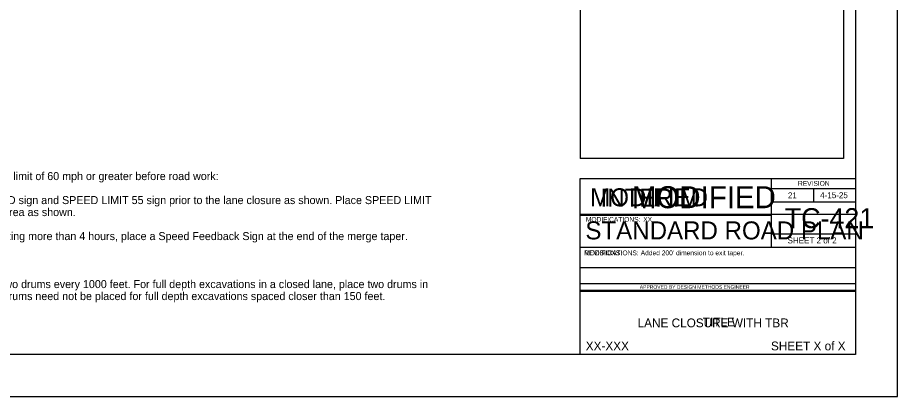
# Model space of a CAD drawing. Extents: x -2135039 to 114557, y -2139150 to -409929.
# Drawn here: x -2130293 to -2128095, y -2139150 to -2138203 of the extents above; entities that cross this region are included whole.
import ezdxf

# ---------------------------------------------------------------- set-up
doc = ezdxf.new("R2010")
doc.units = 0
for name, color, linetype in [('dsnDOTLogo', 7, 'Continuous'), ('dsnNonPlotable', 7, 'Continuous'), ('dsnStdBlock', 7, 'Continuous'), ('dsnstdblockInterim', 7, 'Continuous'), ('dsnStdLogo', 7, 'Continuous'), ('dsnstdModifiedBlock', 7, 'Continuous'), ('Level 1', 7, 'Continuous'), ('Level 12', 7, 'Continuous'), ('StdNote', 7, 'Continuous')]:
    doc.layers.add(name, color=color, linetype=linetype)

msp = doc.modelspace()

# ---------------------------------------------------------------- linework, layer by layer
at = {"layer": 'dsnDOTLogo'}
msp.add_lwpolyline([(-2131438.9, -2139150.4), (-2128095, -2139150.4), (-2128095, -2136566.4), (-2131438.9, -2136566.4)], close=True, dxfattribs=at)
at = {"layer": 'dsnNonPlotable'}
for p, q in [((-2128887.5, -2137085.9), (-2128887.5, -2138555.9)), ((-2128229.5, -2137085.9), (-2128229.5, -2138555.9)), ((-2128229.5, -2138555.9), (-2128887.5, -2138555.9))]:
    msp.add_line(p, q, dxfattribs=at)
at = {"layer": 'dsnStdLogo'}
for p, q in [((-2128410.4, -2138605.9), (-2128410.4, -2138697.3)), ((-2128410.4, -2138630.9), (-2128199.5, -2138630.9)), ((-2128304.9, -2138630.9), (-2128304.9, -2138664.1)), ((-2128410.4, -2138664.1), (-2128199.5, -2138664.1)), ((-2128887.5, -2138697.3), (-2128410.4, -2138697.3)), ((-2128410.4, -2138697.3), (-2128410.4, -2138777.3)), ((-2128199.5, -2138745.1), (-2128410.4, -2138745.1)), ((-2128887.5, -2138777.3), (-2128199.5, -2138777.3)), ((-2128887.5, -2138828.3), (-2128199.5, -2138828.3)), ((-2128887.5, -2138868.3), (-2128199.5, -2138868.3)), ((-2128887.5, -2138887.3), (-2128199.5, -2138887.3))]:
    msp.add_line(p, q, dxfattribs=at)
msp.add_lwpolyline([(-2128887.5, -2138605.9), (-2128199.5, -2138605.9), (-2128199.5, -2139045.9), (-2128887.5, -2139045.9)], close=True, dxfattribs=at)
at = {"layer": 'dsnstdModifiedBlock'}
for p, q in [((-2128887.5, -2138695), (-2128199.5, -2138695)), ((-2128887.5, -2138885), (-2128199.5, -2138885))]:
    msp.add_line(p, q, dxfattribs=at)
msp.add_lwpolyline([(-2128887.5, -2138605.9), (-2128199.5, -2138605.9), (-2128199.5, -2139045.9), (-2128887.5, -2139045.9)], close=True, dxfattribs=at)
at = {"layer": 'Level 1'}
msp.add_lwpolyline([(-2131334.4, -2137035.9), (-2128199.5, -2137035.9), (-2128199.5, -2139045.9), (-2131334.4, -2139045.9)], close=True, dxfattribs=at)
at = {"layer": 'Level 12'}
msp.add_lwpolyline([(-2128887.5, -2138605.9), (-2128199.5, -2138605.9), (-2128199.5, -2139045.9), (-2128887.5, -2139045.9)], close=True, dxfattribs=at)

# ---------------------------------------------------------------- texts
at = {"layer": 'dsnNonPlotable'}
msp.add_text('REVISIONS:', height=12, dxfattribs=at).set_placement((-2128877.5, -2138797.6))
at = {"layer": 'dsnStdBlock'}
for s, height, p in [('MODIFIED', 45, (-2128862.4, -2138675.1)), ('MODIFICATIONS:', 12, (-2128877.5, -2138797.6))]:
    msp.add_text(s, height=height, dxfattribs=at).set_placement(p)
at = {"layer": 'dsnstdblockInterim'}
msp.add_text('INTERIM', height=45, dxfattribs=at).set_placement((-2128836.5, -2138676.3))
at = {"layer": 'dsnStdLogo'}
for s, height, p in [('REVISION', 12, (-2128343.4, -2138623.8)), ('21', 15, (-2128368.4, -2138655.3)), ('4-15-25', 15, (-2128287.9, -2138654.8)), ('TC-421', 50, (-2128376, -2138729.8)), ('STANDARD ROAD PLAN', 45.001, (-2128874.4, -2138757.9)), ('SHEET 2 of 2', 15, (-2128369.3, -2138767.9)), ("Added 200' dimension to exit taper.", 12, (-2128736.1, -2138797.5)), ('APPROVED BY DESIGN METHODS ENGINEER', 9.003, (-2128738.5, -2138881.4)), ('LANE CLOSURE WITH TBR', 22, (-2128744, -2138977.6))]:
    msp.add_text(s, height=height, dxfattribs=at).set_placement(p)
at = {"layer": 'dsnstdModifiedBlock'}
for s, height, p in [('MODIFIED', 55, (-2128758.1, -2138679.9)), ('MODIFICATIONS:', 12, (-2128873.2, -2138713.9)), ('XX', 12, (-2128729.9, -2138713.9)), ('TITLE', 22, (-2128581.1, -2138975.4)), ('XX-XXX', 22, (-2128873.5, -2139035.3)), ('SHEET X of X', 22, (-2128410.8, -2139035.3))]:
    msp.add_text(s, height=height, dxfattribs=at).set_placement(p)
at = {"layer": 'StdNote'}
for s, p in [('For roadways with a posted speed limit of 60 mph or greater before road work:', (-2130718.1, -2138609.6)), ('Place SPEED LIMIT AHEAD sign and SPEED LIMIT 55 sign prior to the lane closure as shown. Place SPEED LIMIT', (-2130638.1, -2138669.6)), ('65 or 70 beyond the work area as shown.', (-2130638.1, -2138699.6)), ('For traffic control zones lasting more than 4 hours, place a Speed Feedback Sign at the end of the merge taper.', (-2130638.1, -2138759.6)), ('For lanes closed to traffic, place two drums every 1000 feet. For full depth excavations in a closed lane, place two drums in ', (-2130718.1, -2138879.6)), ('front of each location. Additional drums need not be placed for full depth excavations spaced closer than 150 feet.', (-2130718.1, -2138909.6))]:
    msp.add_text(s, height=20, dxfattribs=at).set_placement(p)

doc.saveas('drawing.dxf')
